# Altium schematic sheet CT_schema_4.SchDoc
size 396 x 205 mm
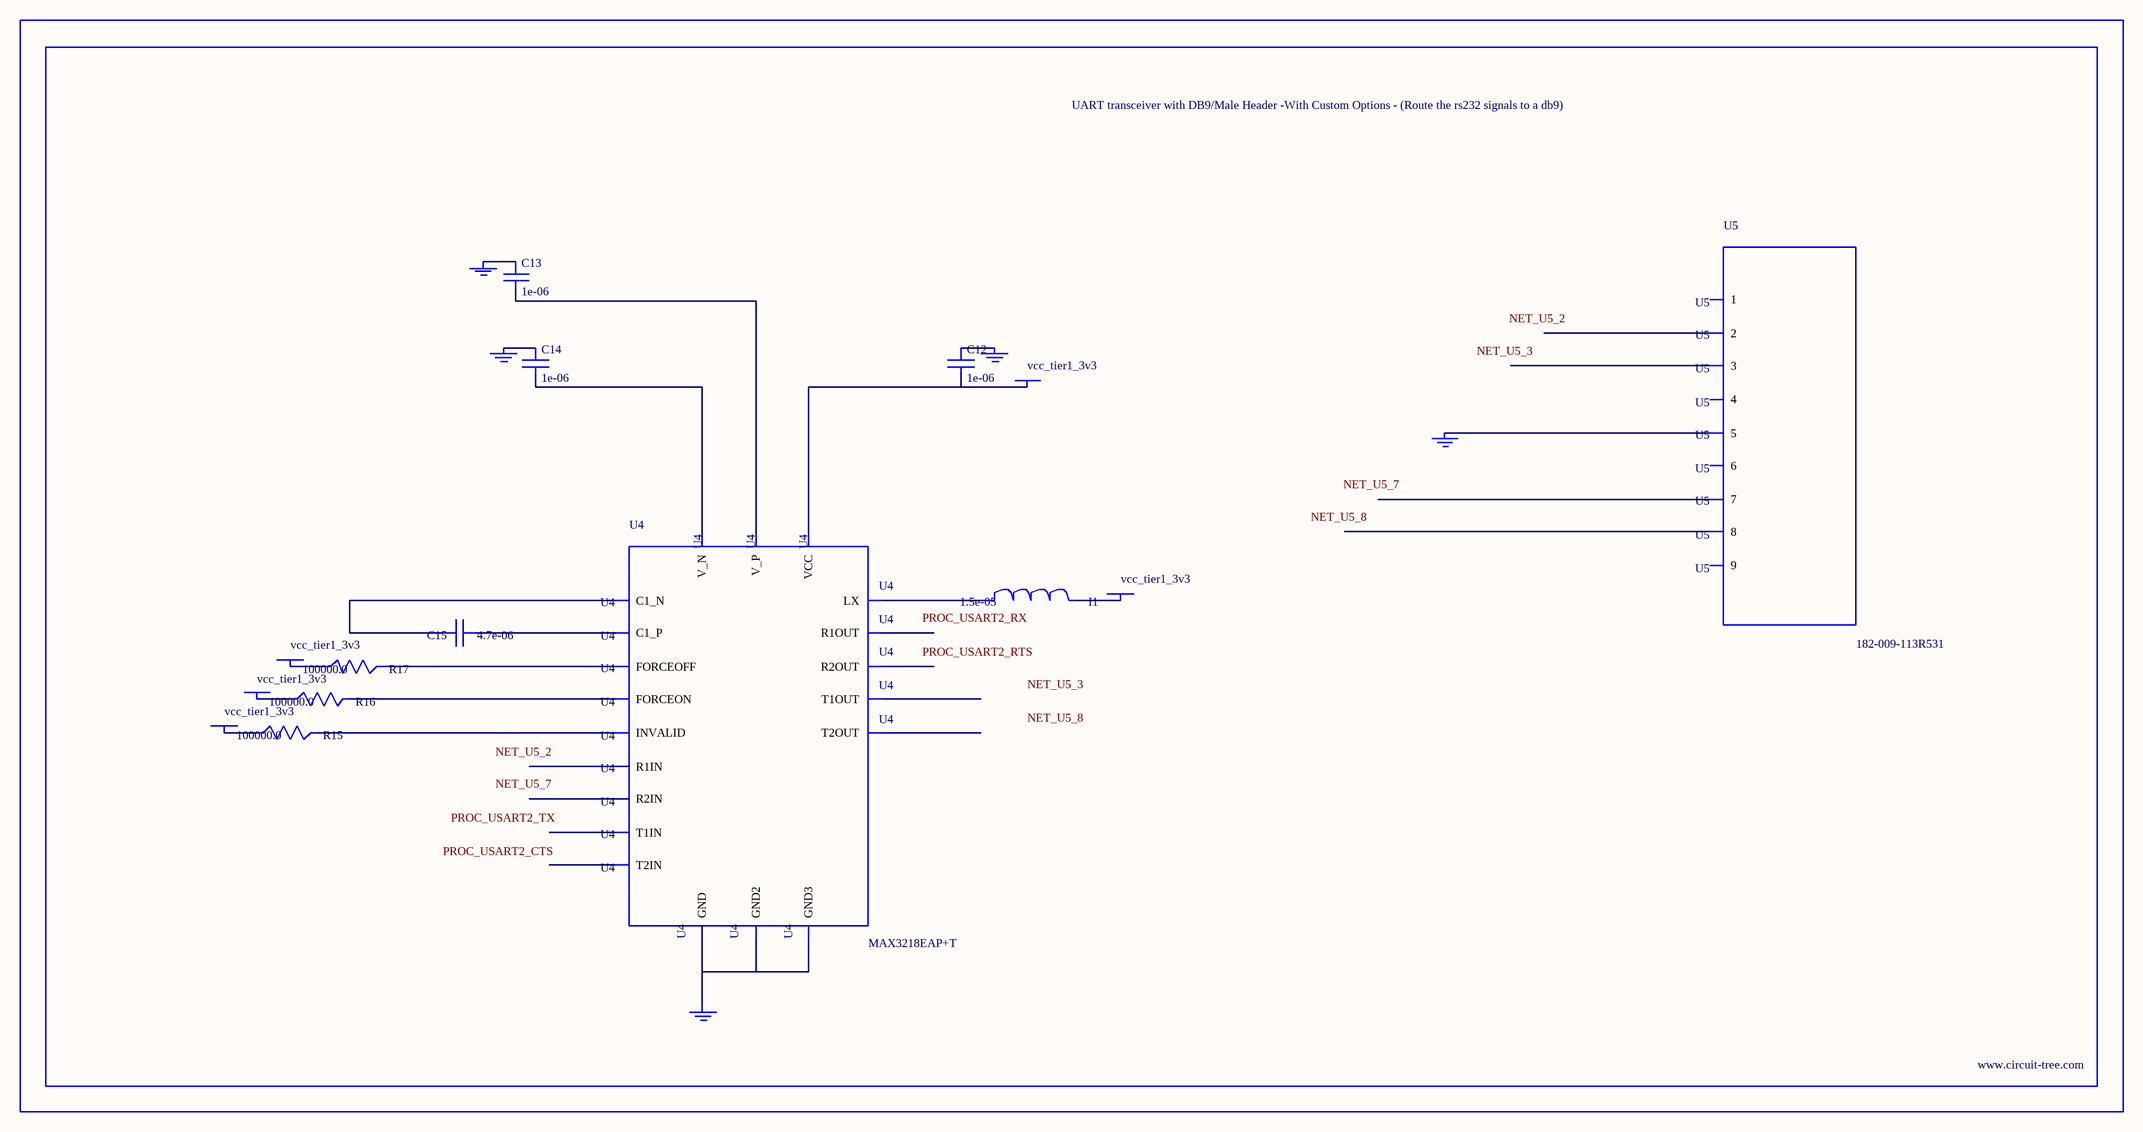
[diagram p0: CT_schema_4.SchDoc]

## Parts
BORDER3  (no value)
C12  1e-06  [C0603]
C13  1e-06  [C0603]
C14  1e-06  [C0603]
C15  4.7e-06  [C0805]
GND_INSTANCE_3_0  (no value)
GND_INSTANCE_3_1  (no value)
GND_INSTANCE_3_2  (no value)
GND_INSTANCE_3_3  (no value)
GND_INSTANCE_3_4  (no value)
I1  1.5e-05  [L1210]
POWER_INSTANCE_3_0  vcc_tier1_3v3
POWER_INSTANCE_3_1  vcc_tier1_3v3
POWER_INSTANCE_3_2  vcc_tier1_3v3
POWER_INSTANCE_3_3  vcc_tier1_3v3
POWER_INSTANCE_3_4  vcc_tier1_3v3
R15  100000.0  [R0603]
R16  100000.0  [R0603]
R17  100000.0  [R0603]
U4  MAX3218EAP+T  [SSOP-20]
U5  182-009-113R531  [182-009-MALE]

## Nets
NetC12_1: C12.1 GND_INSTANCE_3_0.0(GND)
NetC12_2: C12.2 POWER_INSTANCE_3_4.0(PWR) U4.6(VCC)
NetC13_1: C13.1 GND_INSTANCE_3_2.0(GND)
NetC13_2: C13.2 U4.19(V_P)
NetC14_1: C14.1 GND_INSTANCE_3_1.0(GND)
NetC14_2: C14.2 U4.15(V_N)
NetC15_1: C15.1 U4.18(C1_P)
NetC15_2: C15.2 U4.16(C1_N)
NetGND_INSTANCE_3_3_0: GND_INSTANCE_3_3.0(GND) U4.5(GND) U4.17(GND2) U4.20(GND3)
NetGND_INSTANCE_3_4_0: GND_INSTANCE_3_4.0(GND) U5.5
NetI1_1: I1.1 U4.1(LX)
NetI1_2: I1.2 POWER_INSTANCE_3_0.0(PWR)
NetPOWER_INSTANCE_3_1_0: POWER_INSTANCE_3_1.0(PWR) R15.1
NetPOWER_INSTANCE_3_2_0: POWER_INSTANCE_3_2.0(PWR) R16.1
NetPOWER_INSTANCE_3_3_0: POWER_INSTANCE_3_3.0(PWR) R17.1
NetR15_2: R15.2 U4.2(INVALID)
NetR16_2: R16.2 U4.3(FORCEON)
NetR17_2: R17.2 U4.4(FORCEOFF)

Not connected (* = marked no-connect by the designer): U4 7(T1IN) 8(T2IN) 9(R1OUT) 10(R2OUT) 11(R2IN) 12(R1IN) 13(T2OUT) 14(T1OUT); U5 1 2 3 4 6 7 8 9

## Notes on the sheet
- Labels drawn without touching a wire or pin: NET_U5_2, NET_U5_3, NET_U5_7, NET_U5_8, PROC_USART2_CTS, PROC_USART2_RTS, PROC_USART2_RX, PROC_USART2_TX

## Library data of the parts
BORDER3 = BORDER_PAGE3
C12-C14 = C0603C105K3RACTU
C15 = C0805C475K4RACTU
GND_INSTANCE_3_0-GND_INSTANCE_3_4 = GND
I1 = L1210R150MDWIT
POWER_INSTANCE_3_0-POWER_INSTANCE_3_4 = PWR
R15-R17 = RC0603JR-07100KL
